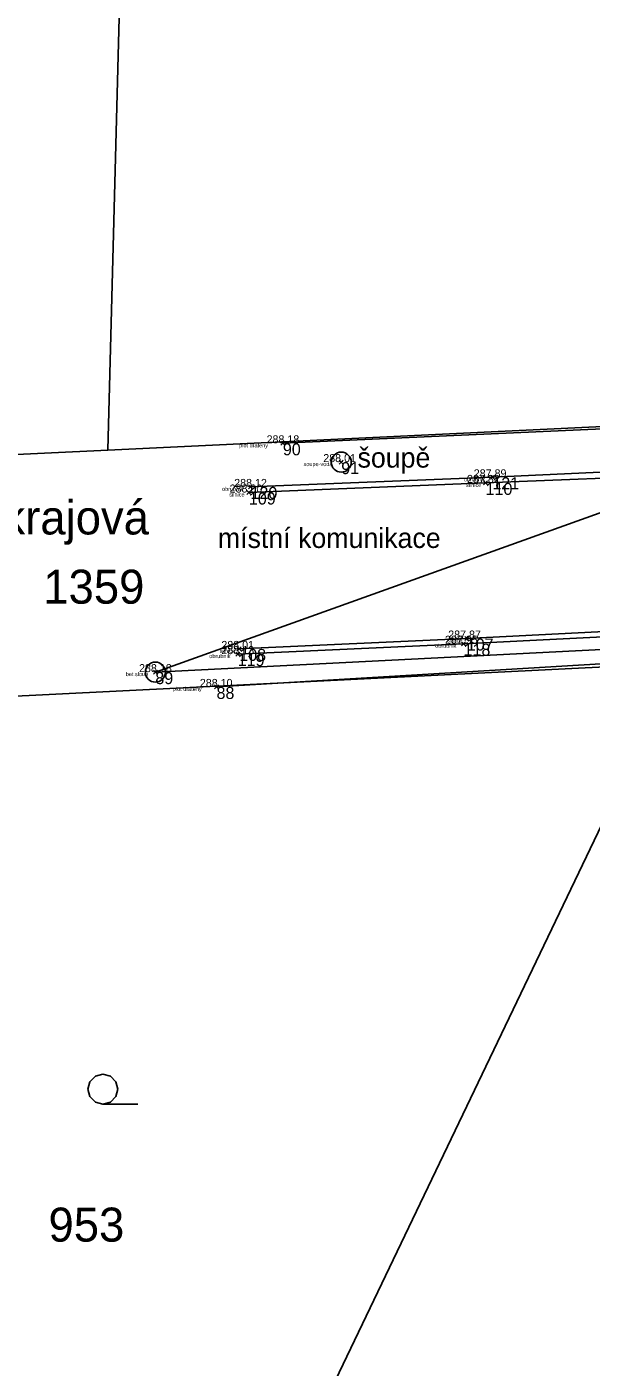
# Model space of a CAD drawing. Extents: x -456675 to -456278, y -1112395 to -1112217.
# Drawn here: x -456364.22 to -456350.1, y -1112322.8 to -1112289.29 of the extents above; entities that cross this region are included whole.
import ezdxf

# ---------------------------------------------------------------- set-up
doc = ezdxf.new("R2010")
doc.units = 0
for name, color, linetype in [('Cislo_bodu', 7, 'Continuous'), ('g_CETIN', 7, 'Continuous'), ('g_elektrina', 7, 'Continuous'), ('g_komunikace', 7, 'Continuous'), ('g_obrubnik', 7, 'Continuous'), ('g_ploty', 7, 'Continuous'), ('g_voda', 7, 'Continuous'), ('Katastralni_mapa', 7, 'Continuous'), ('Kod_bodu', 7, 'Continuous'), ('Vyska_bodu', 7, 'Continuous'), ('Znacka_bodu', 7, 'Continuous')]:
    doc.layers.add(name, color=color, linetype=linetype)

msp = doc.modelspace()

# ---------------------------------------------------------------- linework, layer by layer
at = {"layer": 'g_CETIN'}
msp.add_line((-456361.003, -1112305.42), (-456346.683, -1112300.29), dxfattribs=at)
at = {"layer": 'g_elektrina'}
msp.add_line((-456361.003, -1112305.42), (-456332.123, -1112303.96), dxfattribs=at)
msp.add_circle((-456361.003, -1112305.42), 0.25, dxfattribs=at)
at = {"layer": 'g_komunikace'}
msp.add_lwpolyline([(-456358.663, -1112300.93), (-456352.743, -1112300.69), (-456347.683, -1112300.49), (-456347.653, -1112302.33), (-456347.903, -1112302.36), (-456347.833, -1112303.1), (-456347.723, -1112303.16), (-456347.643, -1112304.3), (-456353.213, -1112304.58), (-456358.903, -1112304.84)], dxfattribs=at)
at = {"layer": 'g_obrubnik'}
for points in [[(-456358.623, -1112300.79), (-456352.573, -1112300.55), (-456347.533, -1112300.31), (-456347.533, -1112302.27)], [(-456358.943, -1112304.97), (-456353.293, -1112304.71), (-456347.643, -1112304.43)]]:
    msp.add_lwpolyline(points, dxfattribs=at)
at = {"layer": 'g_ploty'}
for points in [[(-456357.813, -1112299.7), (-456346.273, -1112299.18), (-456339.333, -1112298.84), (-456333.013, -1112298.52), (-456332.843, -1112291.41), (-456332.833, -1112287.66)], [(-456333.393, -1112317.5), (-456333.293, -1112310.05), (-456333.243, -1112304.42), (-456339.393, -1112304.71), (-456347.913, -1112305.1), (-456359.473, -1112305.79)]]:
    msp.add_lwpolyline(points, dxfattribs=at)
at = {"layer": 'g_voda'}
msp.add_circle((-456356.353, -1112300.17), 0.25, dxfattribs=at)
at = {"layer": 'Katastralni_mapa'}
for points in [[(-456361.893, -1112288.41), (-456362.193, -1112299.87)], [(-456333.073, -1112298.48), (-456362.193, -1112299.87)], [(-456362.193, -1112299.87), (-456368.013, -1112300.15)], [(-456369.703, -1112306.28), (-456347.903, -1112305.2)], [(-456359.693, -1112329.78), (-456347.903, -1112305.2)], [(-456362.313, -1112316.22), (-456362.503, -1112316.17), (-456362.638, -1112316.03), (-456362.688, -1112315.845), (-456362.638, -1112315.66), (-456362.503, -1112315.52), (-456362.313, -1112315.47), (-456362.123, -1112315.52), (-456361.988, -1112315.66), (-456361.938, -1112315.845), (-456361.988, -1112316.03), (-456362.123, -1112316.17), (-456362.313, -1112316.22), (-456361.438, -1112316.22)]]:
    msp.add_lwpolyline(points, dxfattribs=at)
at = {"layer": 'Znacka_bodu'}
for p, q in [((-456357.813, -1112299.7), (-456357.863, -1112299.65)), ((-456357.813, -1112299.7), (-456357.863, -1112299.75)), ((-456357.813, -1112299.7), (-456357.763, -1112299.65)), ((-456357.813, -1112299.7), (-456357.763, -1112299.75)), ((-456356.353, -1112300.17), (-456356.403, -1112300.12)), ((-456356.353, -1112300.17), (-456356.403, -1112300.22)), ((-456356.353, -1112300.17), (-456356.303, -1112300.12)), ((-456356.353, -1112300.17), (-456356.303, -1112300.22)), ((-456358.623, -1112300.79), (-456358.673, -1112300.74)), ((-456358.623, -1112300.79), (-456358.573, -1112300.74)), ((-456352.743, -1112300.69), (-456352.793, -1112300.64)), ((-456352.743, -1112300.69), (-456352.793, -1112300.74)), ((-456352.743, -1112300.69), (-456352.693, -1112300.64)), ((-456352.743, -1112300.69), (-456352.693, -1112300.74)), ((-456352.573, -1112300.55), (-456352.623, -1112300.5)), ((-456352.573, -1112300.55), (-456352.623, -1112300.6)), ((-456352.573, -1112300.55), (-456352.523, -1112300.5)), ((-456352.573, -1112300.55), (-456352.523, -1112300.6)), ((-456358.663, -1112300.93), (-456358.713, -1112300.88)), ((-456358.663, -1112300.93), (-456358.713, -1112300.98)), ((-456358.623, -1112300.79), (-456358.673, -1112300.84)), ((-456358.663, -1112300.93), (-456358.613, -1112300.88)), ((-456358.663, -1112300.93), (-456358.613, -1112300.98)), ((-456358.623, -1112300.79), (-456358.573, -1112300.84)), ((-456353.293, -1112304.71), (-456353.343, -1112304.66)), ((-456353.293, -1112304.71), (-456353.343, -1112304.76)), ((-456353.293, -1112304.71), (-456353.243, -1112304.66)), ((-456353.293, -1112304.71), (-456353.243, -1112304.76)), ((-456353.213, -1112304.58), (-456353.263, -1112304.53)), ((-456353.213, -1112304.58), (-456353.263, -1112304.63)), ((-456353.213, -1112304.58), (-456353.163, -1112304.53)), ((-456353.213, -1112304.58), (-456353.163, -1112304.63)), ((-456358.943, -1112304.97), (-456358.993, -1112304.92)), ((-456358.943, -1112304.97), (-456358.993, -1112305.02)), ((-456358.903, -1112304.84), (-456358.953, -1112304.79)), ((-456358.903, -1112304.84), (-456358.953, -1112304.89)), ((-456358.943, -1112304.97), (-456358.893, -1112304.92)), ((-456358.943, -1112304.97), (-456358.893, -1112305.02)), ((-456358.903, -1112304.84), (-456358.853, -1112304.79)), ((-456358.903, -1112304.84), (-456358.853, -1112304.89)), ((-456361.003, -1112305.42), (-456361.053, -1112305.37)), ((-456361.003, -1112305.42), (-456361.053, -1112305.47)), ((-456361.003, -1112305.42), (-456360.953, -1112305.37)), ((-456361.003, -1112305.42), (-456360.953, -1112305.47)), ((-456359.473, -1112305.79), (-456359.523, -1112305.74)), ((-456359.473, -1112305.79), (-456359.423, -1112305.74)), ((-456359.473, -1112305.79), (-456359.523, -1112305.84)), ((-456359.473, -1112305.79), (-456359.423, -1112305.84))]:
    msp.add_line(p, q, dxfattribs=at)

# ---------------------------------------------------------------- texts
at = {"layer": 'Cislo_bodu'}
for s, p in [('90', (-456357.813, -1112300)), ('91', (-456356.353, -1112300.47)), ('110', (-456352.743, -1112300.99)), ('121', (-456352.573, -1112300.85)), ('109', (-456358.663, -1112301.23)), ('120', (-456358.623, -1112301.09)), ('118', (-456353.293, -1112305.01)), ('107', (-456353.213, -1112304.88)), ('119', (-456358.943, -1112305.27)), ('108', (-456358.903, -1112305.14)), ('89', (-456361.003, -1112305.72)), ('88', (-456359.473, -1112306.09))]:
    msp.add_text(s, height=0.3, dxfattribs=at).set_placement(p)
at = {"layer": 'g_komunikace'}
msp.add_text('místní komunikace', height=0.5, dxfattribs=at).set_placement((-456359.44, -1112302.316))
at = {"layer": 'g_voda'}
msp.add_text('šoupě', height=0.5, dxfattribs=at).set_placement((-456355.946, -1112300.307))
at = {"layer": 'Katastralni_mapa'}
for s, p in [('Okrajová', (-456365.711, -1112301.978)), ('1359', (-456363.806, -1112303.709)), ('953', (-456363.676, -1112319.657))]:
    msp.add_text(s, height=0.85, dxfattribs=at).set_placement(p)
at = {"layer": 'Kod_bodu'}
for s, p in [('plot drateny', (-456358.906, -1112299.8)), ('soupe-voda', (-456357.295, -1112300.27)), ('obrubnik', (-456353.284, -1112300.65)), ('silnice', (-456353.234, -1112300.79)), ('obrubnik', (-456359.334, -1112300.89)), ('silnice', (-456359.154, -1112301.03)), ('obrubnik', (-456354.004, -1112304.81)), ('silnice', (-456353.704, -1112304.68)), ('obrubnik', (-456359.654, -1112305.07)), ('silnice', (-456359.394, -1112304.94)), ('bet.sloup', (-456361.743, -1112305.52)), ('plot drateny', (-456360.566, -1112305.89))]:
    msp.add_text(s, height=0.1, dxfattribs=at).set_placement(p)
at = {"layer": 'Vyska_bodu'}
for s, p in [('288.18', (-456358.221, -1112299.7)), ('288.01', (-456356.803, -1112300.17)), ('287.89', (-456353.039, -1112300.55)), ('288.00', (-456359.145, -1112300.93)), ('288.12', (-456359.031, -1112300.79)), ('287.82', (-456353.208, -1112300.69)), ('287.87', (-456353.678, -1112304.58)), ('288.01', (-456359.353, -1112304.84)), ('288.13', (-456359.351, -1112304.97)), ('287.95', (-456353.759, -1112304.71)), ('288.18', (-456361.411, -1112305.42)), ('288.10', (-456359.89, -1112305.79))]:
    msp.add_text(s, height=0.2, dxfattribs=at).set_placement(p)

doc.saveas('drawing.dxf')
